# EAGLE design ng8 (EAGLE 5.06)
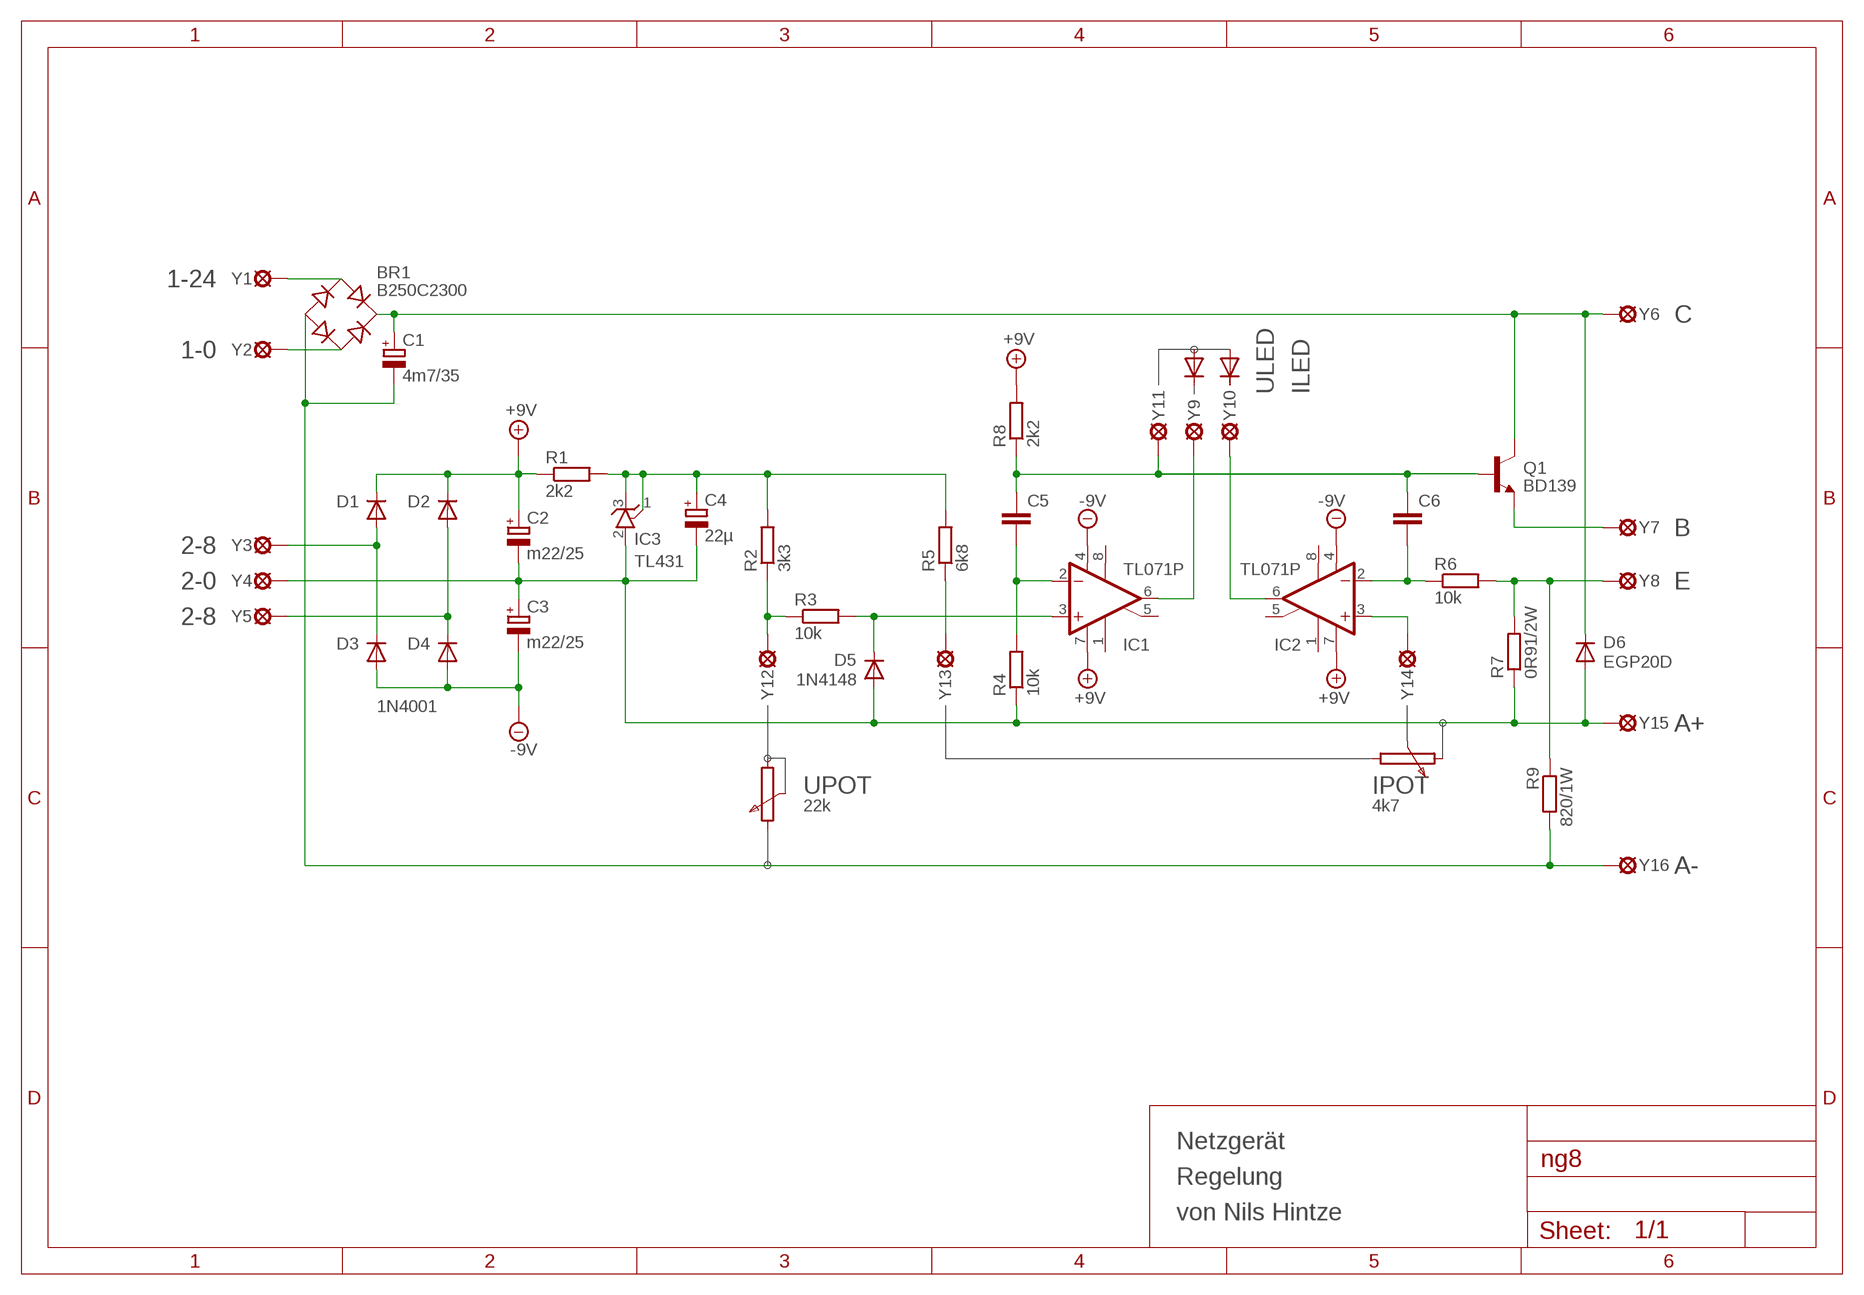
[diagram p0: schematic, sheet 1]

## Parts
BR1  B250C2300  RECTIFIER-2KBP  [2KBP]
C1  4m7/35  CPOL-EUE7.5-18  [E7,5-18]
C2  m22/25  CPOL-EUE3.5-8  [E3,5-8]
C3  m22/25  CPOL-EUE3.5-8  [E3,5-8]
C4  22µ  CPOL-EUTT2D4  [TT2D4]
C5  C-EU050-024X044  [C050-024X044]
C6  C-EU050-024X044  [C050-024X044]
D1  1N4001  1N4004-7  [DO41-7]
D2  1N4001  1N4004-7  [DO41-7]
D3  1N4001  1N4004-7  [DO41-7]
D4  1N4001  1N4004-7  [DO41-7]
D5  1N4148  1N4148DO35-10  [DO35-10]
D6  EGP20D  1N4004-17.5  [DO41-17.5]
IC1  TL071P  [DIL08]
IC2  TL071P  [DIL08]
IC3  TL431  TL431CLP  [TO92-]
Q1  BD139  [TO126]
R1  2k2  R-EU_0207/7  [0207/7]
R2  3k3  R-EU_0207/10  [0207/10]
R3  10k  R-EU_0207/10  [0207/10]
R4  10k  R-EU_0207/12  [0207/12]
R5  6k8  R-EU_0207/7  [0207/7]
R6  10k  R-EU_0207/10  [0207/10]
R7  0R91/2W  R-EU_0207/7  [0207/7]
R8  2k2  R-EU_0207/11  [0207/11]
R9  820/1W  R-EU_0309/V  [0309V]
Y1  MCS10B  [MCS10B]
Y2  MCS10B  [MCS10B]
Y3  MCS10B  [MCS10B]
Y4  MCS10B  [MCS10B]
Y5  MCS10B  [MCS10B]
Y6  MCS10B  [MCS10B]
Y7  MCS10B  [MCS10B]
Y8  MCS10B  [MCS10B]
Y9  MCS10B  [MCS10B]
Y10  MCS10B  [MCS10B]
Y11  MCS10B  [MCS10B]
Y12  MCS10B  [MCS10B]
Y13  MCS10B  [MCS10B]
Y14  MCS10B  [MCS10B]
Y15  MCS10B  [MCS10B]
Y16  MCS10B  [MCS10B]

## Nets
+9V: C2.+ D1.C D2.C IC1.7(V+) IC2.7(V+) R1.1 R8.2
-9V: C3.- D3.A D4.A IC1.4(V-) IC2.4(V-)
AUS+: C2.- C3.+ C4.- D5.A D6.A IC3.2(A) R4.1 R7.1 Y4.MP Y15.MP
AUS-: BR1.- C1.- R9.2 Y16.MP
N$1: BR1.AC1 Y1.MP
N$2: BR1.AC2 Y2.MP
N$3: IC1.6(OUT) Y9.MP
N$4: IC2.6(OUT) Y10.MP
N$5: C6.2 IC2.2(-IN) R6.1
N$6: Q1.1(E) Y7.MP
N$7: C5.1 C6.1 Q1.3(B) R8.1 Y11.MP
N$8: R6.2 R7.2 R9.1 Y8.MP
N$9: IC2.3(+IN) Y14.MP
N$10: D1.A D3.C Y3.MP
N$11: R5.1 Y13.MP
N$12: R2.1 R3.1 Y12.MP
N$14: C5.2 IC1.2(-IN) R4.2
N$15: D5.C IC1.3(+IN) R3.2
N$17: BR1.+ C1.+ D6.C Q1.2(C) Y6.MP
N$20: D2.A D4.C Y5.MP
VREF: C4.+ IC3.1(R) IC3.3(C) R1.2 R2.2 R5.2
Unconnected: IC1.1(ON1) IC1.5(ON2) IC1.8(OPT) IC2.1(ON1) IC2.5(ON2) IC2.8(OPT)

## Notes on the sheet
- 1-24
- C
- 1-0
- ULED | ILED
- B
- 2-8
- 2-0 | E
- 2-8
- A+
- UPOT | IPOT
- 22k | 4k7
- A-
- Netzgerät
- Regelung
- von Nils Hintze

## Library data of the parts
BR1 = nh_rectifier:RECTIFIER-: Rectifier
C1-C4 = nh_rcl:CPOL-EU: POLARIZED CAPACITOR, European symbol
C5 C6 = nh_rcl:C-EU: CAPACITOR, European symbol
D1-D4 D6 = nh_diode:1N4004: DIODE
D5 = nh_diode:1N4148: DIODE
IC1 IC2 = linear:TL071: OP AMP
IC3 = nh-tl431:TL431
Q1 = transistor-npn:BD139*: NPN Transistor
R1-R9 = nh_rcl:R-EU_: RESISTOR, European symbol
Y1-Y16 = solpad:MCS10B: SOLDER PAD

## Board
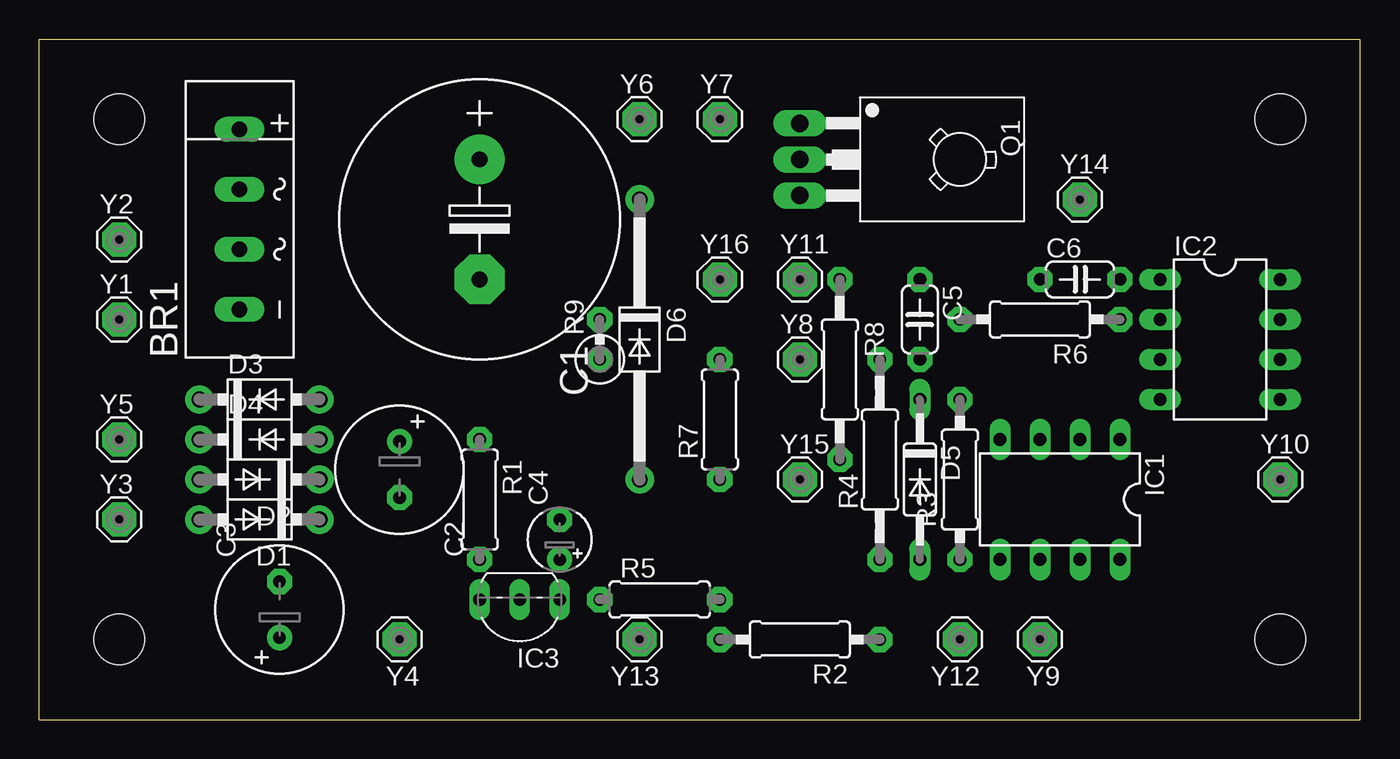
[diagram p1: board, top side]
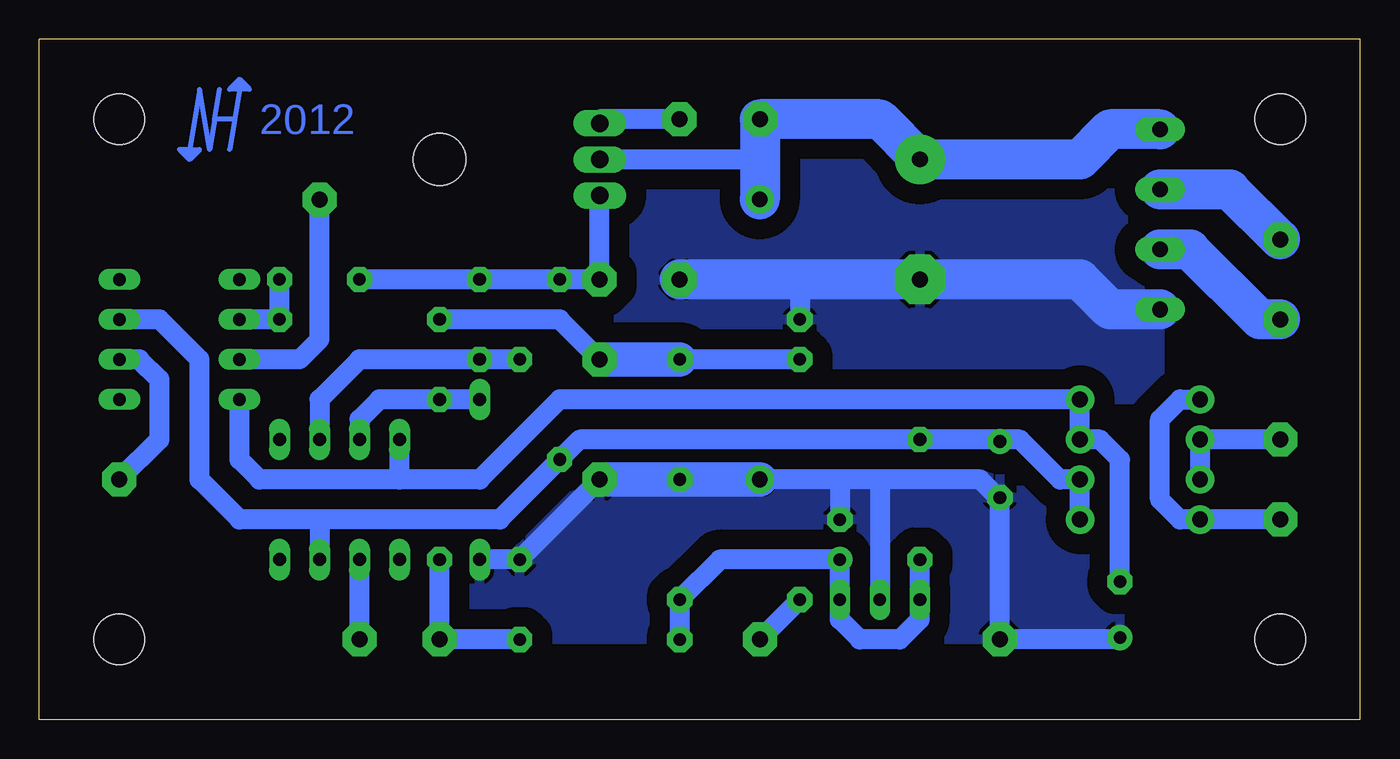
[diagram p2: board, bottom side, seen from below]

Size 83.82 x 43.18 mm. Coordinates in mm from the lower left corner, seen from the top.
Outline: 0,0 0,43.18 83.82,43.18 83.82,0 0,0
Copper layers (1*16): Top 0.035mm / dielectric 1.5mm / Bottom 0.035mm
Design rules "default": minimum track width 10mil, minimum drill 24mil, track to track 8mil, track to pad 8mil, pad to pad 8mil, via to via 8mil, smd to smd 8mil, copper to edge 40mil, drill to drill 8mil, minimum pad ring 10mil, minimum via ring 8mil, stop-mask expansion 4mil, vias tented up to drill 0mil, thermal gap 10mil
Holes 3.2 mm at 5.08,38.1 5.08,5.08 78.74,38.1 78.74,5.08
bRestrict: area 1.3,34.3 to 8.9,41.9; area 1.3,1.3 to 8.9,8.9; area 74.9,34.3 to 82.5,41.9; area 74.9,1.3 to 82.5,8.9

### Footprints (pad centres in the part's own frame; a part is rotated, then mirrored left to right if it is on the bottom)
2KBP = drill 1 pad 1.6 long: + 5.715,0; - -5.715,0; AC1 -1.905,0; AC2 1.905,0
E7,5-18 = drill 1 pad 3.15 round: + -3.81,0 | drill 1 pad 3.15 octagon: - 3.81,0
E3,5-8 = drill 0.8 pad 1.6 round: + -1.778,0 | drill 0.8 pad 1.6 octagon: - 1.778,0
TT2D4 = drill 0.8 pad 1.6 round: + -1.27,0 | drill 0.8 pad 1.6 octagon: - 1.27,0
C050-024X044 = drill 0.8 pad 1.6 octagon: 1 -2.54,0; 2 2.54,0
DO41-7 = drill 1 pad 1.8 round: A 3.81,0; C -3.81,0
DO35-10 = drill 0.813 long: A 5.08,0; C -5.08,0
DO41-17.5 = drill 1 pad 1.8 round: A 8.89,0; C -8.89,0
DIL08 = drill 0.813 long: 1 -3.81,-3.81; 2 -1.27,-3.81; 3 1.27,-3.81; 4 3.81,-3.81; 5 3.81,3.81; 6 1.27,3.81; 7 -1.27,3.81; 8 -3.81,3.81
TO92- = drill 0.8 long: 1 -2.54,0; 2 0,0; 3 2.54,0
TO126 = drill 1.118 long: 1 -2.286,-5.08; 2 0,-5.08; 3 2.286,-5.08 | hole 3.302: 0,5.08
0207/7 = drill 0.8 pad 1.6 octagon: 1 -3.81,0; 2 3.81,0
0207/10 = drill 0.8 pad 1.6 octagon: 1 -5.08,0; 2 5.08,0
0207/12 = drill 0.8 pad 1.6 octagon: 1 -6.35,0; 2 6.35,0
0207/11 = drill 0.8 pad 1.6 octagon: 1 -5.715,0; 2 5.715,0
0309V = drill 0.8 pad 1.6 octagon: 1 -1.27,0; 2 1.27,0
MCS10B = drill 1.016 pad 2.159 octagon: MP 0,0

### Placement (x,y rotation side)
BR1  12.7,31.75 90 top
C1  27.94,31.75 270 top
C2  22.86,15.88 270 top
C3  15.24,6.99 90 top
C4  33.02,11.43 90 top
C5  55.88,25.4 270 top
C6  66.04,27.94 0 top
D1  13.97,12.7 180 top
D2  13.97,15.24 180 top
D3  13.97,20.32 0 top
D4  13.97,17.78 0 top
D5  55.88,15.24 270 top
D6  38.1,24.13 270 top
IC1  64.77,13.97 180 top
IC2  74.93,24.13 270 top
IC3  30.48,7.62 180 top
Q1  53.34,35.56 270 top
R1  27.94,13.97 270 top
R2  48.26,5.08 180 top
R3  58.42,15.24 90 top
R4  53.34,16.51 90 top
R5  39.37,7.62 0 top
R6  63.5,25.4 180 top
R7  43.18,19.05 90 top
R8  50.8,22.23 270 top
R9  35.56,24.13 90 top
Y1  5.08,25.4 0 top
Y2  5.08,30.48 0 top
Y3  5.08,12.7 0 top
Y4  22.86,5.08 180 top
Y5  5.08,17.78 0 top
Y6  38.1,38.1 0 top
Y7  43.18,38.1 0 top
Y8  48.26,22.86 0 top
Y9  63.5,5.08 180 top
Y10  78.74,15.24 0 top
Y11  48.26,27.94 0 top
Y12  58.42,5.08 180 top
Y13  38.1,5.08 180 top
Y14  66.04,33.02 0 top
Y15  48.26,15.24 0 top
Y16  43.18,27.94 0 top

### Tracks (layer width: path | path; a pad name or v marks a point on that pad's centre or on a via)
+9V
  Bottom 1.27: IC2.7 76.2,25.4 73.66,22.86 73.66,15.24 71.12,12.7 66.04,12.7 | 66.04,12.7 IC1.7 | D1.C D2.C 19.05,15.24 21.59,17.78 22.86,17.78 | 22.86,17.78 R1.1 49.53,17.78 R8.2 54.61,12.7 66.04,12.7 | 22.86,17.78 C2.+
-9V
  Bottom 1.27: 60.96,15.24 IC1.4 | C3.- 15.24,16.51 16.51,17.78 D4.A D3.A 50.8,20.32 55.88,15.24 60.96,15.24 | 60.96,15.24 69.85,15.24 71.12,16.51 IC2.4
AUS+
  Bottom 1.27: C3.+ 15.24,5.08 Y4.MP 22.86,13.97 | 22.86,13.97 C2.- | Y15.MP R4.1 D5.A | 22.86,13.97 24.13,15.24 30.48,15.24 | 30.48,15.24 IC3.2 | 30.48,15.24 33.02,15.24 | 33.02,15.24 D6.A | 33.02,15.24 C4.-
  Bottom 2.184: D6.A R7.1 Y15.MP
  pour Bottom (isolate 1.27): 15.24,5.08 15.24,17.78 83.82,17.78 83.82,5.08
AUS-
  Bottom 1.27: 35.56,27.94 R9.2
  Bottom 2.54: Y16.MP 35.56,27.94 C1.- 17.78,27.94 15.88,26.04 BR1.-
  pour Bottom (isolate 1.27): 12.7,20.32 12.7,38.1 83.82,38.1 83.82,20.32
N$1
  Bottom 2.54: Y1.MP 6.35,25.4 10.79,29.84 BR1.AC1
N$2
  Bottom 2.54: BR1.AC2 8.26,33.66 Y2.MP
N$3
  Bottom 1.27: Y9.MP IC1.6
N$4
  Bottom 1.27: IC2.6 77.47,22.86 76.2,21.59 76.2,17.78 Y10.MP
N$5
  Bottom 1.27: C6.2 R6.1 IC2.2
N$6
  Bottom 1.27: Q1.1 48.26,38.1 Y7.MP
N$7
  Bottom 1.27: Q1.3 Y11.MP R8.1 C5.1 C6.1
N$8
  Bottom 1.27: R6.2 50.8,25.4 Y8.MP | R9.1 R7.2
  Bottom 2.184: R7.2 Y8.MP
N$9
  Bottom 1.27: Y14.MP 66.04,24.13 67.31,22.86 IC2.3
N$10
  Bottom 1.27: D3.C 11.43,20.32 12.7,19.05 12.7,13.97 11.43,12.7 D1.A Y3.MP
N$11
  Bottom 1.27: Y13.MP R5.1
N$12
  Bottom 1.27: R3.1 Y12.MP R2.1
N$14
  Bottom 1.27: R4.2 C5.2 63.5,22.86 66.04,20.32 IC1.2
N$15
  Bottom 1.27: IC1.3 63.5,19.05 62.23,20.32 R3.2 D5.C
N$17
  Bottom 1.27: 38.1,35.56 Q1.2
  Bottom 2.54: BR1.+ 15.88,37.47 17.78,35.56 C1.+ 30.48,38.1 Y6.MP 38.1,35.56 D6.C
N$20
  Bottom 1.27: D2.A D4.C Y5.MP
N$25
  Bottom 0.305: 74.3,36.2 73.66,40.01 73.03,36.2 72.71,38.1 | 72.71,38.1 72.39,40.01 | 71.44,38.1 72.71,38.1 | 71.12,40.01 71.44,38.1 | 71.44,38.1 71.75,36.2 | 74.3,36.2 74.93,36.2 | 74.93,36.2 74.3,35.56 | 73.66,36.2 74.3,35.56 | 74.3,36.2 73.66,36.2 | 71.12,40.01 71.75,40.01 | 71.12,40.64 71.75,40.01 | 70.48,40.01 71.12,40.64 | 70.48,40.01 71.12,40.01 | 71.12,40.01 71.12,40.32 | 71.12,40.64 71.12,40.32 | 74.3,36.2 74.3,35.88 | 74.3,35.88 74.3,35.56 | 70.48,40.01 71.12,40.32 | 71.12,40.32 71.75,40.01 | 73.66,36.2 74.3,35.88 | 74.93,36.2 74.3,35.88
VREF
  Bottom 1.27: R1.2 IC3.3 27.94,6.35 29.21,5.08 31.75,5.08 33.02,6.35 IC3.1 C4.+ 40.64,10.16 R5.2 R2.2

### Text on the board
Bottom: 2012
